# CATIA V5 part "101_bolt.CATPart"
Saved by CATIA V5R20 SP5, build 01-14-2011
Part number: 101_bolt
Bounding box of the stored display mesh (mm): x -11 to 11, y 129.409 to 151.315, z -118.5 to -98.85
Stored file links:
  C:\Documents and Settings\anizard\Bureau\13\101_bolt.CATPart
  C:\Documents and Settings\anizard\Bureau\13\anizard.CATProduct
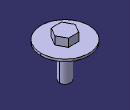
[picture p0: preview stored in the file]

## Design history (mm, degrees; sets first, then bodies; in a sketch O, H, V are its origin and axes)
Set1
  Plane1: linked copy from another document
  Point1: linked copy from another document
Body1 (main body)
  Sketch1 on Plane1, origin (0, 0, -103.5), H (1, 0, 0), V (0, 1, 0)
    circle A1 centre (0, 140.3619) radius 2.5
    reference projected point E1 (0, 140.3619) from Point1
    radius A1 = 2.5
    concentricity: A1 E1
  Pad1: profile Sketch1, direction (0, 0, -1), length 15
  Sketch2 on start face of Pad1, origin (0, 0, -103.5), H (1, 0, 0), V (0, 1, 0)
    circle A1 centre (0, 140.3619) radius 11
    reference projected circle E1 centre (0, 140.3619) radius 2.5 from edge [face of Pad1 from Sketch1.A1 | start face of Pad1]
    radius A1 = 11
    concentricity: A1 E1
  Pad2: profile Sketch2, direction (0, 0, 1), length 1
  Sketch3 on end face of Pad2, origin (0, 0, -102.5), H (1, 0, 0), V (0, 1, 0)
    point P1 (0, 140.3619)
    point P2 (-4.6, 140.3619)
    point P3 (-2.3, 136.3782)
    point P4 (2.3, 136.3782)
    point P5 (4.6, 140.3619)
    point P6 (2.3, 144.3457)
    point P7 (-2.3, 144.3457)
    point P8 (-3.45, 138.3701)
    line L1 (-4.6, 140.3619) -> (-2.3, 136.3782)
    line L2 (-2.3, 136.3782) -> (2.3, 136.3782)
    line L3 (2.3, 136.3782) -> (4.6, 140.3619)
    line L4 (4.6, 140.3619) -> (2.3, 144.3457)
    line L5 (2.3, 144.3457) -> (-2.3, 144.3457)
    line L6 (-2.3, 144.3457) -> (-4.6, 140.3619)
    construction line L7 (0, 140.3619) -> (-3.45, 138.3701)
    construction circle A1 centre (0, 140.3619) radius 4.6
    construction arc A2 centre (2.3, 144.3457) radius 4.6 from (4.6, 140.3619) to (-2.3, 144.3457) cw
    construction arc A3 centre (-2.3, 136.3782) radius 4.6 from (2.3, 136.3782) to (-4.6, 140.3619) ccw
    reference projected circle E1 centre (0, 140.3619) radius 11 from edge [face of Pad2 from Sketch2.A1 | end face of Pad2]
    radius A1 = 4.6
    coincidence: A1 P2, A1 P3, A1 P4, A1 P5, A1 P6, A1 P7, A2 P1, A3 P1
    midpoint: P8 L1
    parallelism: L1 L4
    horizontal: L5 H
    concentricity: E1 A1
  Pad3: profile Sketch3, direction (0, 0, 1), length 3.65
